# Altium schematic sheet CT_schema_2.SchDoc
size 284 x 135 mm
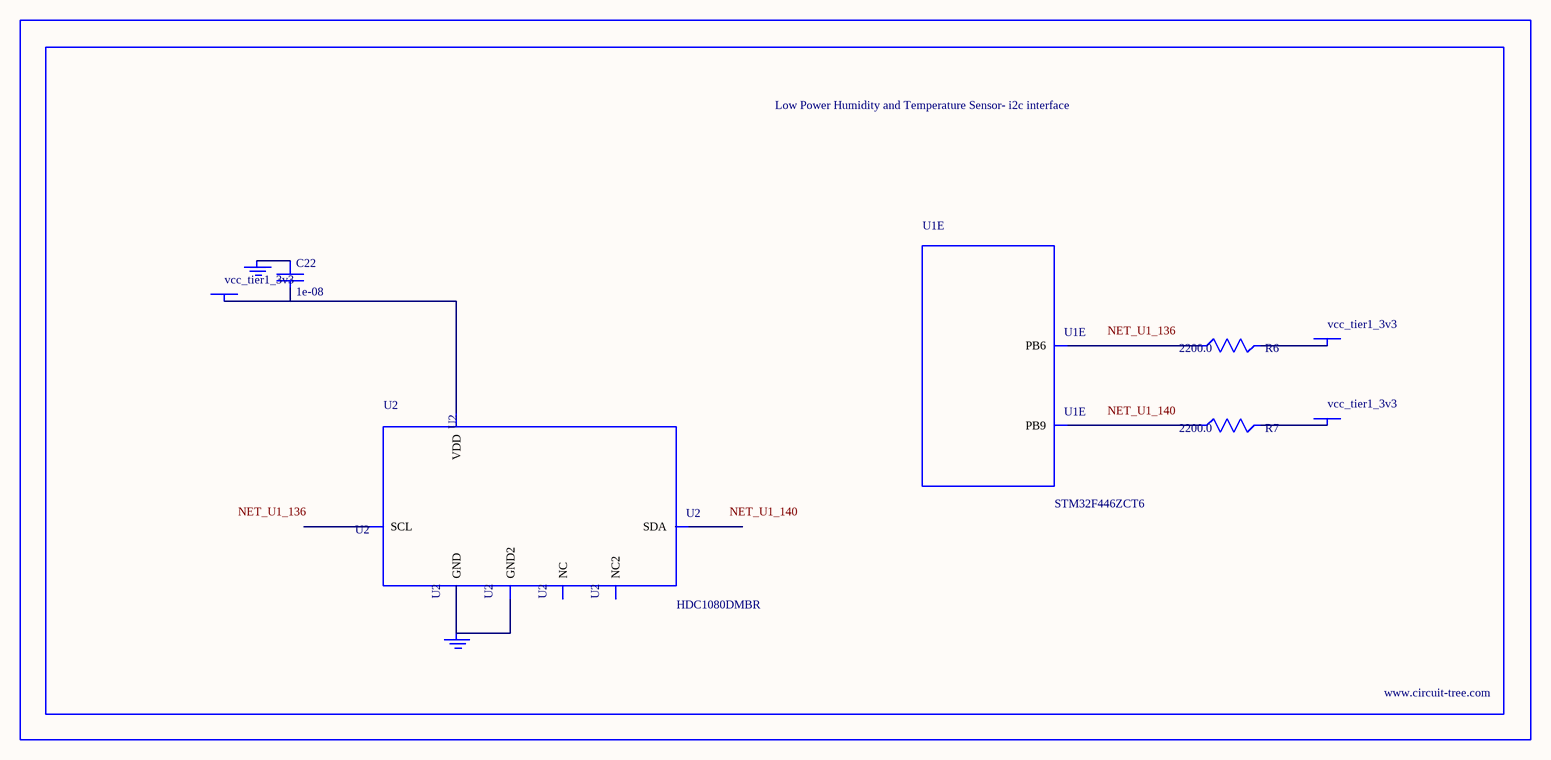
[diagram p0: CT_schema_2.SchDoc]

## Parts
BORDER1  (no value)
C22  1e-08  [C0402]
GND_INSTANCE_1_0  (no value)
GND_INSTANCE_1_1  (no value)
POWER_INSTANCE_1_0  vcc_tier1_3v3
POWER_INSTANCE_1_1  vcc_tier1_3v3
POWER_INSTANCE_1_2  vcc_tier1_3v3
R6  2200.0  [R0603]
R7  2200.0  [R0603]
U1  STM32F446ZCT6  [LQFP144]  (part E of 12)
U2  HDC1080DMBR  [WSON-6]

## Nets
NetC22_1: C22.1 GND_INSTANCE_1_0.0(GND)
NetC22_2: C22.2 POWER_INSTANCE_1_0.0(PWR) U2.5(VDD)
NetGND_INSTANCE_1_1_0: GND_INSTANCE_1_1.0(GND) U2.2(GND) U2.PAD(GND2)
NetPOWER_INSTANCE_1_1_0: POWER_INSTANCE_1_1.0(PWR) R6.2
NetPOWER_INSTANCE_1_2_0: POWER_INSTANCE_1_2.0(PWR) R7.2
NetR6_1: R6.1 U1.136(PB6)
NetR7_1: R7.1 U1.140(PB9)

Not connected (* = marked no-connect by the designer): U2 1(SDA) 3(NC) 4(NC2) 6(SCL)

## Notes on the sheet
- Labels drawn without touching a wire or pin: NET_U1_136, NET_U1_140

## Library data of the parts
BORDER1 = BORDER_PAGE1
C22 = C0402C103K3RAC
GND_INSTANCE_1_0 GND_INSTANCE_1_1 = GND
POWER_INSTANCE_1_0-POWER_INSTANCE_1_2 = PWR
R6 R7 = RC0603JR-072K2L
